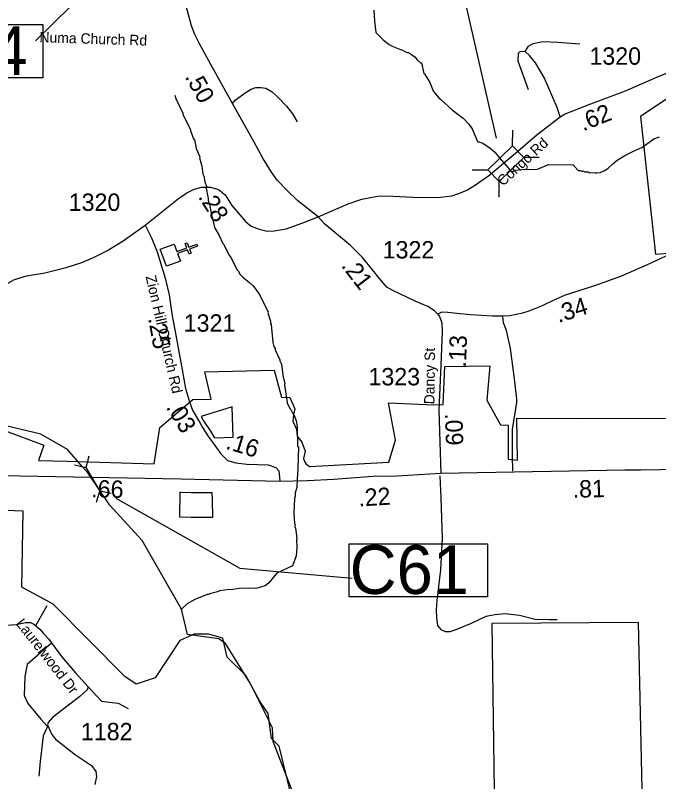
# Model space of a CAD drawing. Extents: x 1248224 to 1454986, y 825081 to 985870.
# Drawn here: x 1346308 to 1350937, y 878480 to 883995 of the extents above; entities that cross this region are included whole.
import ezdxf

# ---------------------------------------------------------------- set-up
doc = ezdxf.new("R2010")
doc.units = 0
for name, color, linetype in [('Exist Boundary Political City Limit New', 7, 'Continuous'), ('Exist Boundary Political City Limit New Hole', 7, 'Continuous'), ('Exist Cultural Church CELL', 7, 'Continuous'), ('Exist Hydrographic Creek Single Shore', 7, 'Continuous'), ('Exist Hydrographic Misc Water Feature', 7, 'Continuous'), ('Exist Road Non-System Type 51', 7, 'Continuous'), ('Exist Road Primary US Mileage Hundredths English Label', 7, 'Continuous'), ('Exist Road Primary US Structure Culvert CELL', 7, 'Continuous'), ('Exist Road Primary US Structure Culvert Number Label', 7, 'Continuous'), ('Exist Road Primary US UnDivided 4 Lane Attributed', 7, 'Continuous'), ('Exist Road Secondary Mileage Hundredths English Label', 7, 'Continuous'), ('Exist Road Secondary Structure Standard Bridge CELL', 7, 'Continuous'), ('Exist Road Secondary Structure Standard Bridge Number Label', 7, 'Continuous'), ('Exist Road Secondary Type 51 Attributed', 7, 'Continuous'), ('Exist Road Secondary Type 51 Label', 7, 'Continuous'), ('Exist Road Secondary Type 51 Number Label', 7, 'Continuous'), ('Map Preparation Boundary City Limit Buffer Line', 7, 'Continuous')]:
    doc.layers.add(name, color=color, linetype=linetype)

msp = doc.modelspace()

# ---------------------------------------------------------------- linework, layer by layer
at = {"layer": 'Exist Boundary Political City Limit New'}
for points in [[(1350995.3, 883393.2), (1350805.8, 883265.8), (1350913.8, 882275.5), (1351102.7, 882290.8)], [(1346218.4, 881010.9), (1346512.3, 880902.3), (1346473.9, 880790.4), (1346681.5, 880787.2), (1347307.6, 880767.8), (1347347.6, 881029), (1347586.6, 881231.2), (1347717.3, 881232.7), (1347670.9, 881429), (1348171.2, 881442.2), (1348223.6, 881246), (1348283.4, 881243.5), (1348305.8, 881196.1), (1348318.3, 881163.6), (1348310.8, 881121.2), (1348305.8, 881073.8), (1348330.7, 881016.4), (1348335.7, 880966.5), (1348370.6, 880924.1), (1348394.4, 880858.5), (1348381.3, 880806.1), (1348387.9, 880783.1), (1348400.8, 880765.4), (1348427.5, 880747.8), (1348994.9, 880778.2), (1349044.2, 880936.4), (1348993.4, 881206), (1349319.3, 881191.8), (1349387.7, 881193.8), (1349399.8, 881468.4), (1349721.7, 881473.1), (1349701.2, 881226.4), (1349799.5, 881048.9), (1349855.2, 881046.5), (1349853.4, 880800), (1349921.7, 880793.8), (1349917.4, 881095.8), (1350393.3, 881093.2), (1351023.3, 881094.9)], [(1347492.8, 879495.2), (1347313.9, 879228.1), (1347177.4, 879182.6), (1347096.2, 879236.5), (1346580.2, 879758), (1346355.2, 879879.5), (1346363.9, 880427.1), (1345370.4, 880464.3)], [(1350820.9, 878315.5), (1350792.6, 879626), (1349738.1, 879618.5), (1349760.5, 877900.5)], [(1348296.6, 878372.2), (1348205.6, 878736.4), (1348151, 878791), (1348126.7, 878970.1), (1348069.1, 879055.1), (1347966, 879243.3), (1347832.5, 879376.8), (1347802.2, 879513.4), (1347699.1, 879540.7), (1347595.9, 879540.7), (1347492.8, 879495.2)]]:
    msp.add_lwpolyline(points, dxfattribs=at)
at = {"layer": 'Exist Boundary Political City Limit New Hole'}
for points in [[(1347742.3, 880953.5), (1347876.1, 880959.7), (1347868, 881176.3), (1347645.7, 881107.5)], [(1347645.7, 881107.5), (1347663.3, 881077), (1347712, 881001.8), (1347742.3, 880953.5)], [(1347573.3, 880382), (1347491.8, 880382.9), (1347494.8, 880563.3)], [(1347494.8, 880563.3), (1347497.1, 880563.2), (1347502.7, 880563), (1347572.7, 880560)], [(1347572.7, 880560), (1347615.7, 880560.1), (1347722.3, 880559.8)], [(1347722.3, 880559.8), (1347723.9, 880503.6), (1347726.1, 880385.6), (1347726.2, 880380.5)], [(1347726.2, 880380.5), (1347612.6, 880381.6), (1347573.3, 880382)]]:
    msp.add_lwpolyline(points, dxfattribs=at)
at = {"layer": 'Exist Cultural Church CELL'}
msp.add_lwpolyline([(1347450.6, 882348.5), (1347470.5, 882295.2), (1347541.9, 882321.7), (1347530.8, 882351.7), (1347545.7, 882357.3), (1347556.9, 882327.3), (1347613.3, 882348.2), (1347618.8, 882333.2), (1347562.5, 882312.2), (1347573.6, 882282.3), (1347558.6, 882276.7), (1347547.5, 882306.7), (1347476.1, 882280.2), (1347496.1, 882226.1), (1347396.3, 882189), (1347350.8, 882311.4)], close=True, dxfattribs=at)
at = {"layer": 'Exist Hydrographic Creek Single Shore'}
for points in [[(1349116, 883733.2), (1349128.2, 883726.8), (1349136.2, 883726.6), (1349152, 883718.3), (1349183.5, 883695.5), (1349199.1, 883675.2), (1349224.5, 883652.5), (1349230.5, 883652.4), (1349248.8, 883576.1), (1349252.8, 883573.6), (1349287.4, 883515.2), (1349318, 883446.5), (1349356.9, 883397.6), (1349370.7, 883389.3), (1349455, 883313.3), (1349529.7, 883255.7), (1349570.8, 883212.7), (1349596, 883178), (1349634, 883087.2), (1349672.9, 883075.5), (1349724, 883038.3), (1349759, 883010.5), (1349789.2, 882972.4), (1349824, 882934.3)], [(1349824, 882934.3), (1349878.9, 882868.1), (1349906.9, 882881.5), (1349954, 882884.9), (1350066, 882888.3), (1350144.5, 882921.9), (1350321.6, 882919.7), (1350357.4, 882878.7), (1350373.4, 882878.4), (1350381.3, 882874.2), (1350397.3, 882873.7), (1350405.2, 882869.6), (1350429.2, 882869), (1350437.2, 882864.8), (1350481.5, 882862.2)], [(1346833.4, 880700.3), (1346790.8, 880745.3), (1346684.3, 880869.9), (1346492.7, 880981), (1346187.9, 881053.5), (1345998.9, 881175.4), (1345892.9, 881292.5), (1345807, 881537.2), (1345703.7, 881775.9)], [(1350000.8, 877966.6), (1349839, 877937), (1349611.1, 877810.2), (1349438, 877531.4), (1349345, 877464.3), (1349145, 877468.3), (1348996, 877530.4), (1348865, 877634.8), (1348697.1, 877956.6), (1348298, 878420.9), (1348164, 878768.3), (1348158, 878867), (1347999, 879188.6), (1347821, 879474.4), (1347772, 879508.3), (1347548, 879539), (1347503.1, 879721.7), (1347221, 880215.3), (1346986.8, 880472.1), (1346833.4, 880700.3)]]:
    msp.add_lwpolyline(points, dxfattribs=at)
at = {"layer": 'Exist Hydrographic Misc Water Feature'}
for points in [[(1348888.2, 884031.6), (1348893.1, 883952.1), (1348903.4, 883871.9), (1348954.2, 883818.7), (1348997.5, 883785.8), (1349019.2, 883773.3), (1349080.6, 883747.9), (1349088.6, 883747.7), (1349116, 883733.2)], [(1347455.3, 883421), (1347462.8, 883396.8), (1347514.5, 883291.6), (1347514.3, 883283.6), (1347567.8, 883170.5), (1347567.6, 883162.5), (1347579.1, 883140.2), (1347588.4, 883110), (1347592.3, 883103.9), (1347598.2, 883101.8), (1347608.8, 883037.5), (1347635.4, 882976.9), (1347633.3, 882969), (1347650, 882908.6), (1347656.8, 882852.4), (1347664.4, 882836.2), (1347671.4, 882796), (1347682.8, 882763.8), (1347682.4, 882749.8), (1347693.1, 882687.6), (1347696.9, 882679.5), (1347696.5, 882663.5), (1347707.6, 882623.3), (1347722, 882546.9), (1347744.1, 882462.4), (1347774.9, 882409.7), (1347801.6, 882353.1), (1347806.5, 882348.7), (1347847.8, 882268), (1347859.5, 882251.8), (1347905.5, 882162.7), (1347913.3, 882154.5), (1347924.8, 882132.3), (1347944.3, 882109.8), (1347995.4, 882070.7), (1348018.9, 882048.1), (1348066.2, 881985.6), (1348126.6, 881857.7), (1348125.5, 881853), (1348145.3, 881793.2), (1348144.9, 881777.2), (1348148.7, 881769.1), (1348161.9, 881640.9), (1348169.3, 881612.7), (1348176.9, 881596.6), (1348176.8, 881588.6), (1348211.1, 881515.8), (1348210.9, 881507.8), (1348222.4, 881483.5), (1348226.1, 881467.4), (1348233, 881402.9), (1348247.3, 881342.9), (1348245.5, 881334.9), (1348264.2, 881206.6), (1348283.4, 881166.1), (1348291.2, 881158), (1348306.5, 881125.6), (1348314.3, 881117.4), (1348329.4, 881077.1), (1348336.4, 881032.9), (1348337.5, 880900.8), (1348339.3, 880890.8), (1348345.2, 880888.7), (1348341.7, 880732.8), (1348336.7, 880654.3), (1348332.7, 880597), (1348321.9, 880557.3), (1348321.3, 880533.3), (1348317, 880517.4), (1348312.7, 880413.4), (1348317, 880337.4), (1348320.8, 880329.3), (1348320.4, 880313.3), (1348324.3, 880305.2), (1348334.7, 880233), (1348332.5, 880225), (1348333.7, 880162.7), (1348327.9, 880105.1), (1348302.3, 880033.7), (1348191, 879980.3), (1348174.7, 879964.6), (1348131.5, 879909.6), (1348107.1, 879890.1), (1348038.6, 879869.7), (1347986.7, 879872.9), (1347918.9, 879870.1), (1347858.4, 879859.8), (1347850.4, 879862), (1347778.3, 879853.6), (1347762.1, 879846.1), (1347713.9, 879835.1), (1347697.7, 879827.5), (1347689.7, 879827.7), (1347600.8, 879789.7), (1347544.2, 879759), (1347503.1, 879721.7)], [(1350481.5, 882862.2), (1350493, 882861.5), (1350517, 882863.1), (1350549.4, 882878.3), (1350573.8, 882895.8), (1350606.5, 882927), (1350639, 882952.3), (1350694.7, 882985.5), (1350756.5, 883017.6), (1350817.1, 883044.1), (1350867.4, 883080.7)], [(1350867.4, 883080.7), (1350902.5, 883106.3), (1350942.8, 883121.3)]]:
    msp.add_lwpolyline(points, dxfattribs=at)
at = {"layer": 'Exist Road Non-System Type 51'}
msp.add_line((1346455.3, 879603.8), (1346537.3, 879748.6), dxfattribs=at)
for points in [[(1346707.1, 884061.5), (1346452.5, 883810.6)], [(1349977, 883734.6), (1350000.7, 883772.4), (1350033.8, 883791.4), (1350104.7, 883805.6), (1350211.1, 883800.8), (1350369.6, 883789)], [(1350227.5, 883264.1), (1350206.4, 883332.2), (1350114.2, 883547.6), (1350050.3, 883654.1), (1350007.8, 883706.2), (1349977, 883734.6), (1349939.2, 883732.2), (1349927.3, 883720.4), (1349925, 883668.3), (1349998.3, 883460)], [(1347870.9, 883359.5), (1347892.4, 883385.9), (1347968.9, 883442.5), (1348005.4, 883462.5), (1348038.3, 883474.3), (1348078.4, 883475.4), (1348111.3, 883470.7), (1348156, 883443.6), (1348201.9, 883400.1), (1348258.4, 883340), (1348302, 883287), (1348337.3, 883228.1)], [(1349889.2, 880714.4), (1349886.8, 880828), (1349884.5, 880939.2), (1349886.8, 881015), (1349896.3, 881074.1), (1349917.6, 881211.4), (1349917.6, 881235.1), (1349898.7, 881398.4), (1349870.3, 881597.2), (1349842.2, 881726.2), (1349820.9, 881783), (1349816.2, 881830.3)], [(1349362.2, 880681.3), (1349370.9, 880521.3), (1349379.6, 880233.2), (1349367.2, 880005.4), (1349341.9, 879782.4), (1349336.6, 879717.1), (1349339.2, 879658.4), (1349345.9, 879603.8), (1349371.2, 879574.5), (1349400.5, 879559.8), (1349437.8, 879561.2), (1349480.4, 879575.8), (1349589.6, 879619.8), (1349696.1, 879670.4), (1349757.4, 879683.8), (1349833.3, 879689.1), (1349937.2, 879678.4), (1350049, 879650.4), (1350148.3, 879646.5), (1350206.9, 879647.8)], [(1346568.4, 879475.8), (1346392.5, 879323.2), (1346376.8, 879237.2), (1346372.9, 879100.3), (1346398.3, 879043.5), (1346492.2, 878930.1), (1346539.1, 878877.3)], [(1346831.6, 879163.4), (1346928.3, 879060.1), (1346983, 879052.2), (1347049.4, 879044.4), (1347119.8, 879005.3)], [(1346539.1, 878877.3), (1346507.8, 878810.8), (1346488.2, 878624.9), (1346476.6, 878519)]]:
    msp.add_lwpolyline(points, dxfattribs=at)
at = {"layer": 'Exist Road Primary US Structure Culvert CELL'}
for p, q in [((1346837.5, 880821.8), (1346814.7, 880741.7)), ((1346733.5, 880760), (1346814.7, 880741.7)), ((1346814.7, 880741.7), (1346916.1, 880571.2)), ((1346893.4, 880491), (1346916.1, 880571.2)), ((1346997.4, 880552.8), (1346916.1, 880571.2))]:
    msp.add_line(p, q, dxfattribs=at)
at = {"layer": 'Exist Road Primary US Structure Culvert Number Label'}
msp.add_lwpolyline([(1347030.8, 880520.1), (1347924.9, 880015.3), (1348732.5, 879943.2)], dxfattribs=at)
msp.add_lwpolyline([(1348710.7, 880190.8), (1349706.1, 880190.8), (1349706.1, 879811), (1348710.7, 879811)], close=True, dxfattribs=at)
at = {"layer": 'Exist Road Primary US UnDivided 4 Lane Attributed'}
for points in [[(1348210.7, 880640.1), (1347499.5, 880656.2), (1346855.7, 880668.8), (1346211.8, 880681.7), (1345764.7, 880691.7), (1345217.5, 880704.3), (1344730.4, 880716)], [(1353632, 880750.5), (1353050.9, 880758.3), (1352562.9, 880758.1), (1351932.8, 880741), (1350808.4, 880720.6), (1350693.8, 880720.6), (1349897.6, 880708.1), (1349369.9, 880698)], [(1349369.9, 880698), (1349053.2, 880679.2), (1348880.4, 880675.4), (1348601.1, 880654.1), (1348410.8, 880645.3), (1348210.7, 880640.1)]]:
    msp.add_lwpolyline(points, dxfattribs=at)
at = {"layer": 'Exist Road Secondary Structure Standard Bridge CELL'}
for p, q in [((1349886.4, 883055), (1349887.6, 883168.1)), ((1349965.5, 882974.1), (1350078.7, 882972.9)), ((1349595.7, 882883.2), (1349708.9, 882881.9)), ((1349788.6, 882686), (1349789.9, 882799.2))]:
    msp.add_line(p, q, dxfattribs=at)
msp.add_lwpolyline([(1349708.9, 882881.9), (1349886, 883055.3), (1349967, 882972.6), (1349789.9, 882799.2)], close=True, dxfattribs=at)
at = {"layer": 'Exist Road Secondary Structure Standard Bridge Number Label'}
msp.add_lwpolyline([(1349770.7, 883110.6), (1349199.7, 885616.6), (1348026, 886695.1)], dxfattribs=at)
msp.add_lwpolyline([(1345862.9, 883928.2), (1346507, 883928.2), (1346507, 883545.9), (1345862.9, 883545.9)], close=True, dxfattribs=at)
at = {"layer": 'Exist Road Secondary Type 51 Attributed'}
for points in [[(1348487.4, 882544.8), (1348340, 882659.8), (1348264.4, 882733.4), (1348192.8, 882809.1), (1348151, 882866.8), (1348089.7, 882967.4), (1348028, 883080.9), (1347972.3, 883180.4), (1347870.9, 883359.5), (1347714, 883641.1), (1347630.5, 883794.3), (1347600.6, 883856.1), (1347576.8, 883919.7), (1347547, 884026.7), (1347503.3, 884168), (1347469.4, 884281.5), (1347443.6, 884349.2), (1347406.3, 884426), (1347379.9, 884470.6), (1347338.2, 884560.2), (1347288.5, 884685.6), (1347264.6, 884745.3), (1347227.2, 884822.8)], [(1349824, 882934.3), (1349891.5, 882987.3), (1350064.3, 883137.5), (1350227.5, 883264.1), (1350263.8, 883286.9), (1350338.1, 883314.2), (1350430.6, 883350.6), (1350698.8, 883452.2), (1350946.6, 883559.4), (1351090.6, 883614), (1351180, 883638.3), (1351278.6, 883670.2), (1351345.3, 883692.9), (1351386.2, 883715.7), (1351413.5, 883736.9), (1351431.5, 883754.8)], [(1348487.4, 882544.8), (1348702.6, 882638.9), (1348801.2, 882670.7), (1348875.4, 882685.9), (1348928.5, 882695), (1349027, 882693.5), (1349219.5, 882684.4), (1349366.5, 882685.9), (1349448.3, 882695), (1349499.9, 882711.7), (1349556, 882737.5), (1349618.7, 882775), (1349721.8, 882847.8), (1349824, 882934.3)], [(1347242, 882485.7), (1347363.6, 882580.6), (1347482.7, 882675.5), (1347543.5, 882716.9), (1347594.5, 882743.6), (1347648, 882758.2), (1347713.6, 882758.2), (1347769.6, 882741.2), (1347818.2, 882702.3), (1347866.8, 882626.8), (1347922.7, 882558.7), (1347964, 882510.1), (1348005.4, 882478.4), (1348063.7, 882456.5), (1348119.6, 882441.9), (1348170.7, 882444.4), (1348258.2, 882459), (1348377.3, 882500.3), (1348487.4, 882544.8)], [(1349348.9, 881844.5), (1349325, 881869.2), (1349276.4, 881899.6), (1349184.6, 881937.9), (1349025.3, 882013.4), (1348980.4, 882038.9), (1348926.9, 882102.2), (1348881.9, 882160.6), (1348806.5, 882253), (1348720.4, 882337.7), (1348535.7, 882492.2), (1348487.4, 882544.8)], [(1345703.7, 881775.9), (1345878, 881850.1), (1345966.3, 881888.1), (1346048.6, 881943.4), (1346149.2, 882008.5), (1346246.1, 882062.5), (1346301.3, 882093.2), (1346389.7, 882119), (1346519.8, 882142.3), (1346674.8, 882179.9), (1346786.5, 882215.5), (1346870, 882251.2), (1346965.7, 882299.1), (1347084.7, 882372.7), (1347242, 882485.7)], [(1347242, 882485.7), (1347288.1, 882393.3), (1347328.6, 882292.6), (1347386.3, 882102.2), (1347414.5, 881982.5), (1347434.1, 881846.2), (1347468.5, 881665.6), (1347508.9, 881442.7), (1347533.4, 881308.3), (1347561.6, 881213.7), (1347583.7, 881152.3), (1347627.4, 881079.3)], [(1351044.1, 882287.1), (1350942.8, 882240.6), (1350918.2, 882229.2)], [(1350918.2, 882229.2), (1350848.7, 882197), (1350662.8, 882114.3), (1350475.6, 882047.4), (1350264.4, 881980.7), (1350178.1, 881941.7), (1350099.1, 881904), (1350003.5, 881865.3), (1349958.5, 881850.7), (1349866.1, 881832.5), (1349816.2, 881830.3), (1349740.9, 881830), (1349584.1, 881839.8), (1349484.9, 881849.5), (1349419.2, 881856.8), (1349377.9, 881858), (1349348.9, 881844.5)], [(1349348.9, 881844.5), (1349361.1, 881827.6), (1349378, 881783), (1349379.6, 881717.7), (1349370.3, 881478), (1349354.6, 881153.8)], [(1349354.6, 881153.8), (1349369.9, 880698)], [(1347627.4, 881079.3), (1347638.9, 881060.2), (1347655.6, 881029.7), (1347692.8, 880969.6), (1347786.8, 880838), (1347834.2, 880791.7), (1347894.4, 880773.5), (1347974, 880765), (1348128.2, 880761.1), (1348183.2, 880740.5), (1348205.2, 880717.1), (1348209.2, 880671.7), (1348210.7, 880640.1)], [(1346248.3, 879606.9), (1346313.4, 879610.6), (1346380.7, 879624.1), (1346416.5, 879624.1), (1346441.3, 879614.4), (1346484, 879577.4), (1346512.2, 879545.5), (1346549.6, 879504.8), (1346639.4, 879380.4), (1346742.1, 879262.4), (1346831.6, 879163.4), (1346824.5, 879141.4), (1346771.7, 879093.5), (1346575.3, 878942.4), (1346544.7, 878904.6), (1346541, 878889.9), (1346544.7, 878878.8), (1346553.3, 878854.2), (1346570.5, 878819.9), (1346597.5, 878786.7), (1346742.1, 878672.3), (1346857.4, 878595.6), (1346886.8, 878553.8), (1346891.8, 878517), (1346879.5, 878460.5)]]:
    msp.add_lwpolyline(points, dxfattribs=at)
at = {"layer": 'Map Preparation Boundary City Limit Buffer Line'}
for points in [[(1350995.3, 883393.2), (1350805.8, 883265.8), (1350913.8, 882275.5), (1351102.7, 882290.8)], [(1346218.4, 881010.9), (1346512.3, 880902.3), (1346473.9, 880790.4), (1346681.5, 880787.2), (1347307.6, 880767.8), (1347347.6, 881029), (1347586.6, 881231.2), (1347717.3, 881232.7), (1347670.9, 881429), (1348171.2, 881442.2), (1348223.6, 881246), (1348283.4, 881243.5), (1348305.8, 881196.1), (1348318.3, 881163.6), (1348310.8, 881121.2), (1348305.8, 881073.8), (1348330.7, 881016.4), (1348335.7, 880966.5), (1348370.6, 880924.1), (1348394.4, 880858.5), (1348381.3, 880806.1), (1348387.9, 880783.1), (1348400.8, 880765.4), (1348427.5, 880747.8), (1348994.9, 880778.2), (1349044.2, 880936.4), (1348993.4, 881206), (1349319.3, 881191.8), (1349387.7, 881193.8), (1349399.8, 881468.4), (1349721.7, 881473.1), (1349701.2, 881226.4), (1349799.5, 881048.9), (1349855.2, 881046.5), (1349853.4, 880800), (1349921.7, 880793.8), (1349917.4, 881095.8), (1350393.3, 881093.2), (1351023.3, 881094.9)], [(1347492.8, 879495.2), (1347313.9, 879228.1), (1347177.4, 879182.6), (1347096.2, 879236.5), (1346580.2, 879758), (1346355.2, 879879.5), (1346363.9, 880427.1), (1345370.4, 880464.3)], [(1350820.9, 878315.5), (1350792.6, 879626), (1349738.1, 879618.5), (1349760.5, 877900.5)], [(1348296.6, 878372.2), (1348205.6, 878736.4), (1348151, 878791), (1348126.7, 878970.1), (1348069.1, 879055.1), (1347966, 879243.3), (1347832.5, 879376.8), (1347802.2, 879513.4), (1347699.1, 879540.7), (1347595.9, 879540.7), (1347492.8, 879495.2)]]:
    msp.add_lwpolyline(points, dxfattribs=at)

# ---------------------------------------------------------------- texts
at = {"layer": 'Exist Road Primary US Mileage Hundredths English Label'}
for s, rotation, p in [('.66', 358.8816, (1346853.3, 880526)), ('.22', 3.405, (1348779.7, 880460)), ('.81', 1.0407, (1350319.3, 880523.5))]:
    msp.add_text(s, height=125, rotation=rotation, dxfattribs=at).set_placement(p)
at = {"layer": 'Exist Road Primary US Structure Culvert Number Label'}
msp.add_text('C61', height=350, dxfattribs=at).set_placement((1348713.9, 879830.8))
at = {"layer": 'Exist Road Secondary Mileage Hundredths English Label'}
for s, rotation, p in [('.50', 299.1259, (1347525.3, 883552.8)), ('.62', 21.7044, (1350393.6, 883159.9)), ('.28', 302.8075, (1347619.9, 882688.3)), ('.21', 307.604, (1348648.7, 882191.5)), ('.34', 17.5367, (1350216.4, 881780.4)), ('.25', 280.275, (1347263.4, 881813.7)), ('.13', 87.7991, (1349550.5, 881458.6)), ('.03', 300.9432, (1347389.5, 881174.9)), ('.09', 271.9309, (1349399.4, 881129.3)), ('.16', 343.1604, (1347815.9, 880877.3))]:
    msp.add_text(s, height=125, rotation=rotation, dxfattribs=at).set_placement(p)
at = {"layer": 'Exist Road Secondary Structure Standard Bridge Number Label'}
msp.add_text('74', height=350, dxfattribs=at).set_placement((1345875.4, 883565.7))
at = {"layer": 'Exist Road Secondary Type 51 Label'}
for s, rotation, p in [('Numa Church Rd', 358.1813, (1346481, 883801.2)), ('Congo Rd', 42.4553, (1349816.8, 882761.2)), ('Zion Hill Church Rd', 282.9209, (1347245.2, 882115)), ('Dancy St', 89.3933, (1349324.2, 881195.2)), ('Laurelwood Dr', 308.0189, (1346308, 879616.8))]:
    msp.add_text(s, height=75, rotation=rotation, dxfattribs=at).set_placement(p)
at = {"layer": 'Exist Road Secondary Type 51 Number Label'}
for s, p in [('1320', (1350439, 883639.3)), ('1320', (1346692.3, 882587.6)), ('1322', (1348951.2, 882245.1)), ('1321', (1347519.7, 881718)), ('1323', (1348849.1, 881331.8)), ('1182', (1346780, 878777.7))]:
    msp.add_text(s, height=125, dxfattribs=at).set_placement(p)

doc.saveas('drawing.dxf')
